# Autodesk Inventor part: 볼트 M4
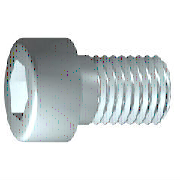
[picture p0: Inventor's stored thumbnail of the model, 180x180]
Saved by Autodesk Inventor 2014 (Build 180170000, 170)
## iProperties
IsCustomPart: 0
Created: 2012-02
Part Number: 볼트 M4
Material: 스테인리스강
Description: 6각 소켓 머리 캡 나사
Document SubType Name: Modeling
Standard: ISO 4762
Designer: mduedu
Standard Revision: Fourth edition 2004-03-01
Standards Organization: ISO
Language: ko-KR
Size Designation: M4 x 12
Categories: <MemberInstance><Categories><Category DisplayName="조임쇠" InternalName="e4da775c-781d-43d5-af7c-5136215cf5a6" Mnemonic="FSTN"><Category DisplayName="볼트" InternalN
Density: 8.08 g/cm^3
Mass: 2.29719 g
Surface Area: 3.30853 cm^2
Volume: 0.284306 cm^3
Appearance: 반광택
Author: mduedu
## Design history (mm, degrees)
sketch "스케치1"
  geometry: L1 (-1, 0)-(12, 0); L2 (12, 0)-(12, 2); L3 (12, 2)-(1.75, 2); L4 (1.75, 2)-(1.32, 2); L5 (1.32, 2)-(0, 2); L6 (0, 2)-(0, 3.5); L7 (0, 3.5)-(-4, 3.5); L8 (-4, 3.5)-(-4, 1.732); L9 (-4, 1.732)-(-2, 1.732); L10 (-2, 1.732)-(-1, 0); L11 (-7.2, 0)-(15.2, 0) reference; L12 (0, -0.7)-(0, 4.2) reference; L13 (1.75, 2)-(0, 2)
  constraints: 22 end point, 6 parallel, 2 collinear, 2 perpendicular, 1 horizontal, 1 point on line
  dimensions: "d1" = 10.25 distance from line of L3.end L2 (= GEL); "d2" = 0.42952 distance of L4.end L3.end (computed from GAL); "d3" = 4 distance between parallel lines of L8 L6 (= KOH); "d4" = 2 distance of L8.end L9.end (= INTI); "d5" = 60 deg angle of L10 L1; "d6" = 4 diameter of L3 L1 (= GD); "d7" = 4 diameter of L5 L1 (= BDM); "d8" = 3.4641 diameter of L9 L1 (= 1.1547 x SW); "d9" = 7 diameter of L7 L1 (= KOD); "d26" = 12 distance between parallel lines of L12 L2 (= NLG)
revolve "본체" sketch "스케치1" stored, may be unused: angle "d10" = 90 deg
sketch "스케치2"
  geometry: L1 (0, -4.9)-(0, 4.9) reference; L2 (-4.9, 0)-(4.9, 0) reference; L3 (1.732, 0)-(0.866, -1.5); L4 (0.866, -1.5)-(-0.866, -1.5); L5 (-0.866, -1.5)-(-1.732, 0); L6 (-1.732, 0)-(-0.866, 1.5); L7 (-0.866, 1.5)-(0.866, 1.5); L8 (0.866, 1.5)-(1.732, 0); 2 further points
  constraints: 12 end point, 1 coincident, 1 horizontal alignment, 1 point on line, 12 other
extrude "슬롯" join sketch "스케치2" stored distance "d11" = 10; taper "d12" = 0 deg
workplane "Work Plane1"
fillet "Fillet2" dims "d30" = 0.1 (= R)
body "Solid1"
fillet "모깎기1" dims "d17" = 0.4 (= RR)
feature "스레드" dims "d13" = 10.25 (= GEL), "d14" = 0
chamfer "모따기1" distance "d15" = 0.42941 (= -0.5 x SPD + 0.5 x GD); stored, may be unused: second distance "d16" = 0.42941 (= GUL), angle "d27" = 45 deg
other parameters: "GD" = 4 [user parameter; used in 2 equation terms], "NLG" = 12 [user parameter; used in 1 equation term], "GEL" = 10.25 [user parameter; used in 2 equation terms], "KOD" = 7 [user parameter; used in 1 equation term], "KOH" = 4 [user parameter; used in 1 equation term], "INTI" = 2 [user parameter; used in 1 equation term], "GAL" = 0.42941 (= 0.61345 x PTC) [user parameter; used in 1 equation term], "GUL" = 0.42941 (= 0.61345 x PTC) [user parameter; used in 1 equation term], "BDM" = 4 (= NND) [user parameter; used in 1 equation term], "SW" = 3 [user parameter; used in 2 equation terms], "RR" = 0.4 [user parameter; used in 1 equation term], "SPD" = 3.14117 (= NND - 1.2269 x PTC) [user parameter; used in 1 equation term], "d19" = 0, "d28" = 0, "d29" = 0, "R" = 0.1 [user parameter; used in 1 equation term], "TOA" = 30 deg [user parameter], "GD1" = 3.14117 (= THREADDIA - 1.2269 x PTC) [user parameter], "THREADDIA" = 4 [user parameter; used in 1 equation term], "FAWI" = 45 deg [user parameter], "TPU" = 14.28571 (computed from PTC) [user parameter], "PTC" = 0.7 [user parameter; used in 5 equation terms], "NND" = 4 [user parameter; used in 2 equation terms], "E0" = 3.465 (= 1.155 x SW) [user parameter]
